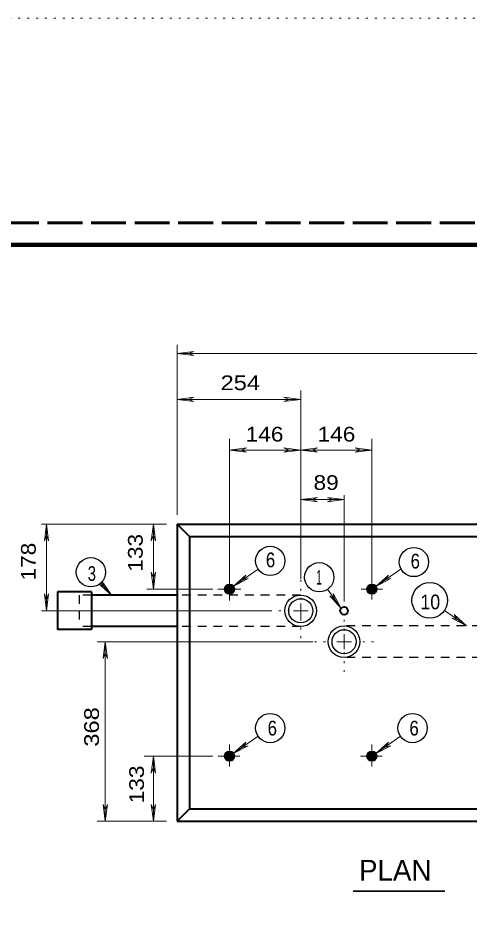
# Model space of a CAD drawing. Extents: x 312583 to 312854, y 144419 to 144597.
# Drawn here: x 312713.43 to 312736.75, y 144550.14 to 144596.78 of the extents above; entities that cross this region are included whole.
import ezdxf
from ezdxf.enums import TextEntityAlignment as Align

# ---------------------------------------------------------------- set-up
doc = ezdxf.new("R2010")
doc.units = 0
doc.header["$LTSCALE"] = 0.3
for name, pattern in [('DOTTED', [1.5, 0.3, -1.2]), ('LONG_DASHED', [7.5, 6, -1.5]), ('SHORT_DASHED', [2.7, 1.5, -1.2])]:
    doc.linetypes.add(name, pattern=pattern)
for name, color, linetype, lineweight in [('1', 7, 'Continuous', 25), ('2', 7, 'Continuous', 13), ('63', 7, 'DOTTED', 13)]:
    doc.layers.add(name, color=color, linetype=linetype, lineweight=lineweight)

msp = doc.modelspace()

# ---------------------------------------------------------------- linework, layer by layer
at = {"layer": '1', "linetype": 'LONG_DASHED', "lineweight": 60}
msp.add_line((312851.75, 144586.2246), (312583.526, 144586.2246), dxfattribs=at)
at = {"layer": '1', "lineweight": 40}
for p, q in [((312721.6325, 144570.6666), (312761.2385, 144570.6666)), ((312721.6325, 144570.6666), (312721.6325, 144555.3333)), ((312722.2688, 144570.0303), (312721.6325, 144570.6666)), ((312722.2688, 144570.0303), (312760.6021, 144570.0303)), ((312722.2688, 144570.0303), (312722.2688, 144555.9773)), ((312717.2241, 144567.1706), (312715.4685, 144567.1706)), ((312715.4685, 144567.1706), (312715.4685, 144565.2233)), ((312717.2241, 144567.1706), (312717.2241, 144565.2233)), ((312721.6325, 144567.0096), (312717.2241, 144567.0096)), ((312717.2241, 144565.2233), (312715.4685, 144565.2233)), ((312721.6325, 144565.3843), (312717.2241, 144565.3843)), ((312721.6325, 144555.3333), (312722.2688, 144555.9773)), ((312722.2688, 144555.9773), (312760.6021, 144555.9773)), ((312721.6325, 144555.3333), (312761.2385, 144555.3333))]:
    msp.add_line(p, q, dxfattribs=at)
at = {"layer": '1', "linetype": 'SHORT_DASHED'}
for p, q in [((312716.5878, 144567.0096), (312716.5878, 144565.3843)), ((312717.2241, 144567.0096), (312716.5878, 144567.0096)), ((312728.0188, 144567.0096), (312721.6325, 144567.0096)), ((312717.2241, 144565.3843), (312716.5878, 144565.3843)), ((312728.0188, 144565.3843), (312721.6325, 144565.3843)), ((312739.7411, 144565.4149), (312730.2575, 144565.4149)), ((312739.7411, 144563.7819), (312730.2575, 144563.7819))]:
    msp.add_line(p, q, dxfattribs=at)
at = {"layer": '1', "lineweight": 158}
msp.add_lwpolyline([(312616.5, 144423.1446), (312616.5, 144585.0846), (312849, 144585.0846)], dxfattribs=at)
at = {"layer": '1', "lineweight": 40}
for centre, radius in [((312724.3446, 144567.3144), 0.2396), ((312731.6918, 144567.3144), 0.2396), ((312724.3446, 144567.3144), 0.2156), ((312724.3446, 144567.3144), 0.1941), ((312724.3446, 144567.3144), 0.1747), ((312724.3446, 144567.3144), 0.1572), ((312724.3446, 144567.3144), 0.1415), ((312724.3446, 144567.3144), 0.1273), ((312724.3446, 144567.3144), 0.1146), ((312724.3446, 144567.3144), 0.1031), ((312724.3446, 144567.3144), 0.0928), ((312724.3446, 144567.3144), 0.0835), ((312724.3446, 144567.3144), 0.0752), ((312724.3446, 144567.3144), 0.0677), ((312724.3446, 144567.3144), 0.0609), ((312724.3446, 144567.3144), 0.0548), ((312731.6918, 144567.3144), 0.2156), ((312731.6918, 144567.3144), 0.1941), ((312731.6918, 144567.3144), 0.1747), ((312731.6918, 144567.3144), 0.1572), ((312731.6918, 144567.3144), 0.1415), ((312731.6918, 144567.3144), 0.1273), ((312731.6918, 144567.3144), 0.1146), ((312731.6918, 144567.3144), 0.1031), ((312731.6918, 144567.3144), 0.0928), ((312731.6918, 144567.3144), 0.0835), ((312731.6918, 144567.3144), 0.0752), ((312731.6918, 144567.3144), 0.0677), ((312731.6918, 144567.3144), 0.0609), ((312731.6918, 144567.3144), 0.0548), ((312730.2543, 144566.1963), 0.1996), ((312724.3446, 144558.6894), 0.2396), ((312724.3446, 144558.6894), 0.2156), ((312724.3446, 144558.6894), 0.1941), ((312724.3446, 144558.6894), 0.1747), ((312724.3446, 144558.6894), 0.1572), ((312724.3446, 144558.6894), 0.1415), ((312724.3446, 144558.6894), 0.1273), ((312724.3446, 144558.6894), 0.1146), ((312724.3446, 144558.6894), 0.1031), ((312724.3446, 144558.6894), 0.0928), ((312724.3446, 144558.6894), 0.0835), ((312724.3446, 144558.6894), 0.0752), ((312724.3446, 144558.6894), 0.0677), ((312724.3446, 144558.6894), 0.0609), ((312724.3446, 144558.6894), 0.0548), ((312731.6918, 144558.6894), 0.2396), ((312731.6918, 144558.6894), 0.2156), ((312731.6918, 144558.6894), 0.1941), ((312731.6918, 144558.6894), 0.1747), ((312731.6918, 144558.6894), 0.1572), ((312731.6918, 144558.6894), 0.1415), ((312731.6918, 144558.6894), 0.1273), ((312731.6918, 144558.6894), 0.1146), ((312731.6918, 144558.6894), 0.1031), ((312731.6918, 144558.6894), 0.0928), ((312731.6918, 144558.6894), 0.0835), ((312731.6918, 144558.6894), 0.0752), ((312731.6918, 144558.6894), 0.0677), ((312731.6918, 144558.6894), 0.0609), ((312731.6918, 144558.6894), 0.0548)]:
    msp.add_circle(centre, radius, dxfattribs=at)
at = {"layer": '1'}
for centre, radius in [((312728.0182, 144566.1963), 0.8146), ((312728.0182, 144566.1963), 0.6232), ((312730.2543, 144564.5991), 0.8146), ((312730.2543, 144564.5991), 0.6232)]:
    msp.add_circle(centre, radius, dxfattribs=at)
at = {"layer": '2'}
for p, q in [((312721.6325, 144571.1573), (312721.6325, 144579.9279)), ((312721.6325, 144579.4756), (312722.4988, 144579.5829)), ((312721.6325, 144579.4756), (312761.2385, 144579.4756)), ((312721.6325, 144579.4756), (312722.4988, 144579.3683)), ((312722.4988, 144579.5829), (312722.2228, 144579.4756)), ((312722.4988, 144579.3683), (312722.2228, 144579.4756)), ((312728.0188, 144567.8529), (312728.0188, 144577.5589)), ((312721.6325, 144577.1066), (312722.4988, 144577.2139)), ((312721.6325, 144577.1066), (312722.4988, 144576.9993)), ((312721.6325, 144577.1066), (312728.0188, 144577.1066)), ((312722.4988, 144577.2139), (312722.2228, 144577.1066)), ((312722.4988, 144576.9993), (312722.2228, 144577.1066)), ((312727.1525, 144577.2139), (312727.4285, 144577.1066)), ((312728.0188, 144577.1066), (312727.1525, 144577.2139)), ((312727.1525, 144576.9993), (312727.4285, 144577.1066)), ((312728.0188, 144577.1066), (312727.1525, 144576.9993)), ((312724.3465, 144567.7609), (312724.3465, 144575.0749)), ((312731.6911, 144567.7609), (312731.6911, 144575.0749)), ((312724.3465, 144574.4923), (312725.2128, 144574.5996)), ((312725.2128, 144574.5996), (312724.9368, 144574.4923)), ((312727.1525, 144574.5996), (312727.4285, 144574.4923)), ((312728.0188, 144574.4923), (312727.1525, 144574.5996)), ((312728.0188, 144574.4923), (312728.8851, 144574.5996)), ((312728.8851, 144574.5996), (312728.6091, 144574.4923)), ((312730.8248, 144574.5996), (312731.1008, 144574.4923)), ((312731.6911, 144574.4923), (312730.8248, 144574.5996)), ((312724.3465, 144574.4923), (312728.0188, 144574.4923)), ((312724.3465, 144574.4923), (312725.2128, 144574.3849)), ((312725.2128, 144574.3849), (312724.9368, 144574.4923)), ((312727.1525, 144574.3849), (312727.4285, 144574.4923)), ((312728.0188, 144574.4923), (312727.1525, 144574.3849)), ((312728.0188, 144574.4923), (312731.6911, 144574.4923)), ((312728.0188, 144574.4923), (312728.8851, 144574.3849)), ((312728.8851, 144574.3849), (312728.6091, 144574.4923)), ((312730.8248, 144574.3849), (312731.1008, 144574.4923)), ((312731.6911, 144574.4923), (312730.8248, 144574.3849)), ((312728.0188, 144571.9316), (312728.8851, 144572.0389)), ((312728.0188, 144571.9316), (312730.2575, 144571.9316)), ((312728.0188, 144571.9316), (312728.8851, 144571.8243)), ((312728.8851, 144572.0389), (312728.6091, 144571.9316)), ((312728.8851, 144571.8243), (312728.6091, 144571.9316)), ((312729.3911, 144572.0389), (312729.6671, 144571.9316)), ((312730.2575, 144571.9316), (312729.3911, 144572.0389)), ((312729.3911, 144571.8243), (312729.6671, 144571.9316)), ((312730.2575, 144571.9316), (312729.3911, 144571.8243)), ((312730.2575, 144566.6799), (312730.2575, 144572.1693)), ((312721.0881, 144570.6666), (312714.6405, 144570.6666)), ((312714.8935, 144570.6666), (312714.7861, 144569.8003)), ((312714.8935, 144566.1969), (312714.8935, 144570.6666)), ((312714.8935, 144570.6666), (312715.0008, 144569.8003)), ((312720.4135, 144570.6666), (312720.3061, 144569.8003)), ((312720.4135, 144567.3163), (312720.4135, 144570.6666)), ((312720.4135, 144570.6666), (312720.5208, 144569.8003)), ((312714.7861, 144569.8003), (312714.8935, 144570.0763)), ((312715.0008, 144569.8003), (312714.8935, 144570.0763)), ((312720.3061, 144569.8003), (312720.4135, 144570.0763)), ((312720.5208, 144569.8003), (312720.4135, 144570.0763)), ((312720.3061, 144568.1826), (312720.4135, 144567.9066)), ((312720.4135, 144567.3163), (312720.3061, 144568.1826)), ((312720.5208, 144568.1826), (312720.4135, 144567.9066)), ((312720.4135, 144567.3163), (312720.5208, 144568.1826)), ((312725.8261, 144568.3436), (312724.5381, 144567.4543)), ((312724.5381, 144567.4543), (312725.1898, 144568.0369)), ((312725.1898, 144568.0369), (312725.0288, 144567.7916)), ((312733.1938, 144568.3589), (312731.8905, 144567.4543)), ((312731.8905, 144567.4543), (312732.5421, 144568.0369)), ((312732.5421, 144568.0369), (312732.3735, 144567.7916)), ((312717.5921, 144567.5846), (312717.8605, 144567.4466)), ((312718.2591, 144567.0096), (312717.5921, 144567.5846)), ((312717.6995, 144567.6229), (312718.2591, 144567.0096)), ((312717.7531, 144567.7226), (312717.8605, 144567.4466)), ((312718.2591, 144567.0096), (312717.7531, 144567.7226)), ((312724.3465, 144566.7259), (312724.3465, 144567.9143)), ((312724.5381, 144567.4543), (312725.3125, 144567.8606)), ((312725.3125, 144567.8606), (312725.0288, 144567.7916)), ((312731.6911, 144566.7719), (312731.6911, 144567.8759)), ((312731.8905, 144567.4543), (312732.6648, 144567.8606)), ((312732.6648, 144567.8606), (312732.3735, 144567.7916)), ((312723.4801, 144567.3163), (312720.0685, 144567.3163)), ((312724.9291, 144567.3163), (312723.7408, 144567.3163)), ((312729.4065, 144567.3086), (312730.0965, 144566.3196)), ((312729.6901, 144567.0939), (312729.7591, 144566.8026)), ((312730.0965, 144566.3196), (312729.6901, 144567.0939)), ((312732.2355, 144567.3163), (312731.1315, 144567.3163)), ((312714.7861, 144567.0633), (312714.8935, 144566.7873)), ((312714.8935, 144566.1969), (312714.7861, 144567.0633)), ((312715.0008, 144567.0633), (312714.8935, 144566.7873)), ((312714.8935, 144566.1969), (312715.0008, 144567.0633)), ((312729.5138, 144566.9636), (312729.7591, 144566.8026)), ((312730.0965, 144566.3196), (312729.5138, 144566.9636)), ((312726.4548, 144566.1969), (312714.6405, 144566.1969)), ((312728.0188, 144566.1969), (312727.6355, 144566.1969)), ((312728.0188, 144566.1969), (312728.0188, 144566.5803)), ((312728.0188, 144566.1969), (312728.4021, 144566.1969)), ((312728.0188, 144566.1969), (312728.0188, 144565.8136)), ((312735.4325, 144566.2123), (312736.5748, 144565.4149)), ((312735.8081, 144565.8213), (312736.0918, 144565.7523)), ((312736.5748, 144565.4149), (312735.8081, 144565.8213)), ((312735.9308, 144565.9976), (312736.0918, 144565.7523)), ((312736.5748, 144565.4149), (312735.9308, 144565.9976)), ((312730.2575, 144564.6023), (312730.2575, 144564.9856)), ((312728.6398, 144564.6023), (312717.5155, 144564.6023)), ((312717.9295, 144564.6023), (312717.8221, 144563.7359)), ((312717.9295, 144555.3333), (312717.9295, 144564.6023)), ((312717.9295, 144564.6023), (312718.0368, 144563.7359)), ((312730.2575, 144564.6023), (312729.8741, 144564.6023)), ((312730.2575, 144564.6023), (312730.6408, 144564.6023)), ((312730.2575, 144564.6023), (312730.2575, 144564.2189)), ((312717.8221, 144563.7359), (312717.9295, 144564.0119)), ((312718.0368, 144563.7359), (312717.9295, 144564.0119)), ((312725.8261, 144559.7186), (312724.5381, 144558.8293)), ((312733.1708, 144559.7186), (312731.8905, 144558.8293)), ((312724.3465, 144558.1623), (312724.3465, 144559.2893)), ((312724.5381, 144558.8293), (312725.1898, 144559.4119)), ((312724.5381, 144558.8293), (312725.3125, 144559.2356)), ((312725.1898, 144559.4119), (312725.0288, 144559.1666)), ((312725.3125, 144559.2356), (312725.0288, 144559.1666)), ((312731.6911, 144558.1623), (312731.6911, 144559.2893)), ((312731.8905, 144558.8293), (312732.5421, 144559.4119)), ((312731.8905, 144558.8293), (312732.6648, 144559.2356)), ((312732.5421, 144559.4119), (312732.3735, 144559.1666)), ((312732.6648, 144559.2356), (312732.3735, 144559.1666)), ((312723.4801, 144558.6913), (312719.9458, 144558.6913)), ((312720.4135, 144558.6913), (312720.3061, 144557.8249)), ((312720.4135, 144555.3333), (312720.4135, 144558.6913)), ((312720.4135, 144558.6913), (312720.5208, 144557.8249)), ((312724.8755, 144558.6913), (312723.7485, 144558.6913)), ((312732.2201, 144558.6913), (312731.0931, 144558.6913)), ((312720.3061, 144557.8249), (312720.4135, 144558.1009)), ((312720.5208, 144557.8249), (312720.4135, 144558.1009)), ((312717.8221, 144556.1996), (312717.9295, 144555.9236)), ((312717.9295, 144555.3333), (312717.8221, 144556.1996)), ((312718.0368, 144556.1996), (312717.9295, 144555.9236)), ((312717.9295, 144555.3333), (312718.0368, 144556.1996)), ((312720.3061, 144556.1996), (312720.4135, 144555.9236)), ((312720.4135, 144555.3333), (312720.3061, 144556.1996)), ((312720.5208, 144556.1996), (312720.4135, 144555.9236)), ((312720.4135, 144555.3333), (312720.5208, 144556.1996)), ((312721.0881, 144555.3333), (312717.5155, 144555.3333))]:
    msp.add_line(p, q, dxfattribs=at)
at = {"layer": '2', "linetype": 'DOTTED'}
for p, q in [((312728.0188, 144566.7719), (312728.0188, 144567.8529)), ((312727.4438, 144566.1969), (312726.4548, 144566.1969)), ((312728.0188, 144564.7786), (312728.0188, 144565.8136)), ((312730.2575, 144565.1773), (312730.2575, 144565.8519)), ((312729.2915, 144564.6023), (312728.6398, 144564.6023)), ((312731.2158, 144564.6023), (312731.8675, 144564.6023)), ((312730.2575, 144563.0383), (312730.2575, 144564.2189))]:
    msp.add_line(p, q, dxfattribs=at)
at = {"layer": '2', "lineweight": 35}
msp.add_line((312730.729, 144551.7216), (312735.4478, 144551.7216), dxfattribs=at)
at = {"layer": '2', "lineweight": 25}
for centre, radius in [((312726.4433, 144568.771), 0.7557), ((312733.8589, 144568.7135), 0.7557), ((312717.1915, 144568.1858), 0.7557), ((312728.972, 144567.9258), 0.7557), ((312734.6754, 144566.7336), 0.9185), ((312726.4433, 144560.146), 0.7557), ((312733.7905, 144560.146), 0.7557)]:
    msp.add_circle(centre, radius, dxfattribs=at)
at = {"layer": '63'}
msp.add_line((312601.2, 144596.7846), (312853.5, 144596.7846), dxfattribs=at)

# ---------------------------------------------------------------- texts
at = {"layer": '2'}
for s, width, p in [('254 ', 1.2, (312723.8796, 144577.5831)), ('146 ', 1.15, (312725.1756, 144574.9314)), ('146 ', 1.15, (312728.8837, 144574.9314)), ('89 ', 1.15, (312728.6767, 144572.434)), ('6', 0.85, (312726.2178, 144568.4429)), ('6', 0.85, (312733.6875, 144568.3816)), ('3', 0.75, (312717.0255, 144567.7404)), ('1', 0.5, (312728.8223, 144567.5435)), ('10', 0.9, (312734.1939, 144566.2727)), ('6', 0.85, (312726.3112, 144559.7618)), ('6', 0.85, (312733.626, 144559.7618))]:
    msp.add_text(s, height=0.76, dxfattribs=dict(at, width=width)).set_placement(p)
for s, width, p in [('133 ', 1.15, (312719.8629, 144568.213)), ('178 ', 1.15, (312714.343, 144567.7576)), ('368 ', 1.2, (312717.603, 144559.1862)), ('133 ', 1.15, (312719.9261, 144556.262))]:
    msp.add_text(s, height=0.76, rotation=90, dxfattribs=dict(at, width=width)).set_placement(p)
msp.add_text('PLAN', height=1.07, dxfattribs=at).set_placement((312732.8953, 144552.2743), align=Align.CENTER)

doc.saveas('drawing.dxf')
